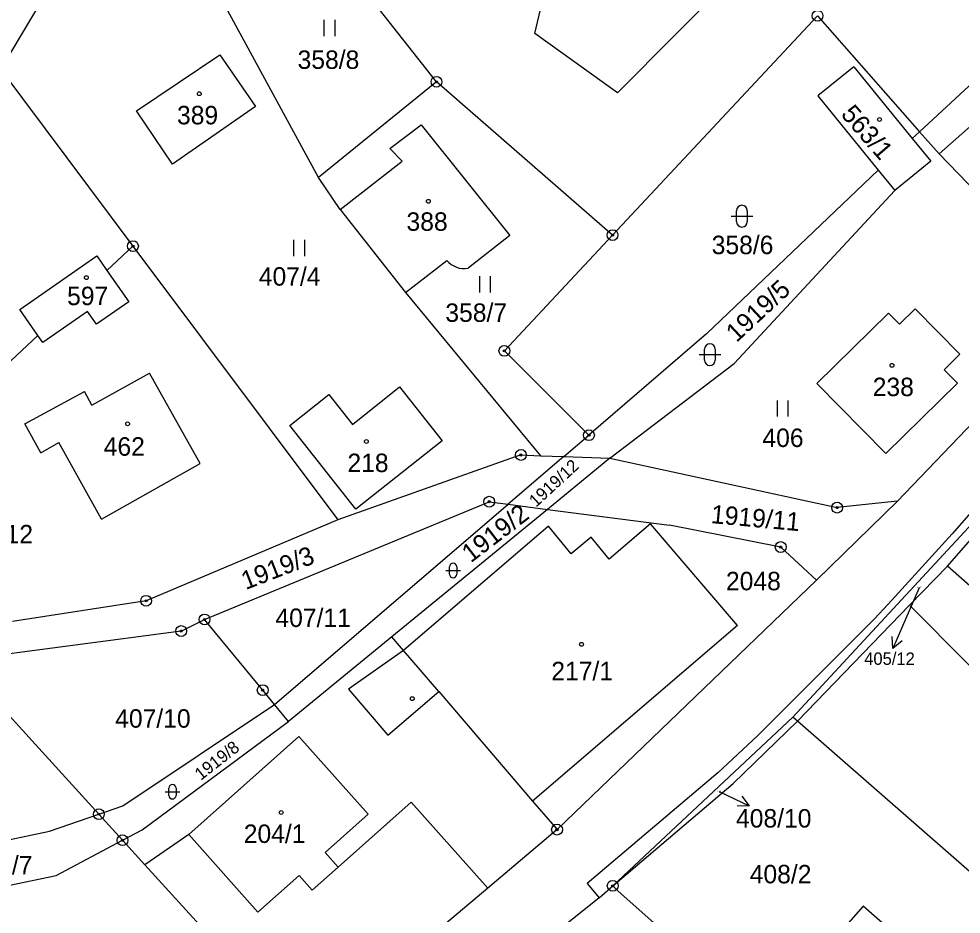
# Model space of a CAD drawing. Extents: x -445050 to -440454, y -1134563 to -1129741.
# Drawn here: x -442831.5 to -442744.7, y -1131095.9 to -1131013.5 of the extents above; entities that cross this region are included whole.
import ezdxf

# ---------------------------------------------------------------- set-up
doc = ezdxf.new("R2010")
doc.units = 0
for name, color, linetype in [('Vrstva 1', 7, 'Continuous'), ('Vrstva 16', 7, 'Continuous'), ('Vrstva 18', 7, 'Continuous'), ('Vrstva 19', 7, 'Continuous'), ('Vrstva 24', 7, 'Continuous'), ('Vrstva 25', 7, 'Continuous'), ('Vrstva 3', 7, 'Continuous'), ('Vrstva 37', 7, 'Continuous'), ('Vrstva 4', 7, 'Continuous'), ('Vrstva 6', 7, 'Continuous')]:
    doc.layers.add(name, color=color, linetype=linetype)

msp = doc.modelspace()

# ---------------------------------------------------------------- linework, layer by layer
at = {"layer": 'Vrstva 1'}
for points in [[(-442833.2, -1131018.12), (-442820.71, -1130997.18)], [(-442680.45, -1130998.49), (-442682.49, -1130998.44), (-442687.19, -1131000.32), (-442692.62, -1131004.7), (-442700.9, -1131011.92), (-442710.05, -1131020.8), (-442718.64, -1131029.65), (-442729.58, -1131042.35), (-442734.04, -1131047.81), (-442745.5, -1131060.91), (-442751.07, -1131067.01), (-442752.63, -1131068.7), (-442763.45, -1131079.5), (-442767.1, -1131082.91), (-442779.14, -1131093.12), (-442778.04, -1131094.43)], [(-442754.98, -1130998.74), (-442776.36, -1131020.27)], [(-442793.04, -1131019.25), (-442805.78, -1131003.06)], [(-442783.98, -1131014.8), (-442781.38, -1131003.85)], [(-442748.51, -1131023.86), (-442727.43, -1131004.32)], [(-442725.82, -1131007.43), (-442746.72, -1131025.9)], [(-442803.93, -1131028.07), (-442812.87, -1131011.62)], [(-442757.92, -1131013.17), (-442776.81, -1131033.38)], [(-442757.92, -1131013.17), (-442748.51, -1131023.86)], [(-442776.36, -1131020.27), (-442783.98, -1131014.8)], [(-442820.69, -1131021.93), (-442813, -1131016.75)], [(-442813, -1131016.75), (-442809.71, -1131021.54)], [(-442754.57, -1131017.86), (-442757.88, -1131020.55)], [(-442754.57, -1131017.86), (-442749.18, -1131024.48)], [(-442833.2, -1131018.12), (-442821.02, -1131034.39)], [(-442793.04, -1131019.25), (-442803.93, -1131028.07)], [(-442776.81, -1131033.38), (-442793.04, -1131019.25)], [(-442757.88, -1131020.55), (-442752.34, -1131027.38)], [(-442817.37, -1131026.85), (-442820.69, -1131021.93)], [(-442809.71, -1131021.54), (-442817.37, -1131026.85)], [(-442797.33, -1131025.41), (-442794.44, -1131023.2)], [(-442794.44, -1131023.2), (-442786.28, -1131033.41)], [(-442749.18, -1131024.48), (-442748.51, -1131023.86)], [(-442748.51, -1131023.86), (-442746.72, -1131025.9)], [(-442749.18, -1131024.48), (-442747.48, -1131026.57)], [(-442796.19, -1131026.56), (-442797.33, -1131025.41)], [(-442801.91, -1131031.02), (-442796.19, -1131026.56)], [(-442747.48, -1131026.57), (-442750.8, -1131029.27)], [(-442746.72, -1131025.9), (-442741.4, -1131031.39)], [(-442752.34, -1131027.38), (-442768.15, -1131042.47)], [(-442752.34, -1131027.38), (-442750.8, -1131029.27)], [(-442801.91, -1131031.02), (-442803.93, -1131028.07)], [(-442765.6, -1131045.19), (-442750.8, -1131029.27)], [(-442801.91, -1131031.02), (-442795.89, -1131038.66)], [(-442786.28, -1131033.41), (-442790.12, -1131036.43)], [(-442776.81, -1131033.38), (-442786.78, -1131044.04)], [(-442823.41, -1131036.63), (-442821.02, -1131034.39)], [(-442821.02, -1131034.39), (-442802.14, -1131059.61)], [(-442829.79, -1131042.61), (-442831.45, -1131040.22), (-442824.34, -1131035.29), (-442823.41, -1131036.63)], [(-442795.89, -1131038.66), (-442792.09, -1131035.7)], [(-442823.41, -1131036.63), (-442821.41, -1131039.52)], [(-442795.89, -1131038.66), (-442783.46, -1131053.7)], [(-442821.41, -1131039.52), (-442824.38, -1131041.57), (-442825.2, -1131040.4), (-442829.33, -1131043.26), (-442829.79, -1131042.61)], [(-442751.37, -1131040.56), (-442757.97, -1131047.05)], [(-442750.36, -1131041.58), (-442751.37, -1131040.56)], [(-442748.92, -1131040.16), (-442750.36, -1131041.58)], [(-442744.79, -1131044.36), (-442748.92, -1131040.16)], [(-442750.55, -1131057.88), (-442734.37, -1131040.99)], [(-442845.58, -1131057.41), (-442829.79, -1131042.61)], [(-442768.15, -1131042.47), (-442778.99, -1131051.81)], [(-442786.78, -1131044.04), (-442778.99, -1131051.81)], [(-442746.24, -1131045.78), (-442744.79, -1131044.36)], [(-442777.06, -1131053.94), (-442765.6, -1131045.19)], [(-442745.02, -1131047.02), (-442746.24, -1131045.78)], [(-442824.8, -1131049.04), (-442819.5, -1131046.1)], [(-442814.83, -1131054.43), (-442819.5, -1131046.1)], [(-442800.79, -1131050.81), (-442796.45, -1131047.37)], [(-442796.45, -1131047.37), (-442792.52, -1131052.34)], [(-442751.62, -1131053.5), (-442757.97, -1131047.05)], [(-442745.02, -1131047.02), (-442751.62, -1131053.5)], [(-442830.97, -1131050.75), (-442825.49, -1131047.77)], [(-442824.8, -1131049.04), (-442825.49, -1131047.77)], [(-442806.55, -1131050.91), (-442802.96, -1131048.07)], [(-442802.96, -1131048.07), (-442800.79, -1131050.81)], [(-442829.51, -1131053.45), (-442830.97, -1131050.75)], [(-442800.46, -1131058.62), (-442806.55, -1131050.91)], [(-442781.3, -1131053.78), (-442778.99, -1131051.81)], [(-442735.52, -1131051.16), (-442760.18, -1131077.8)], [(-442745.94, -1131063.87), (-442735.13, -1131051.5)], [(-442829.51, -1131053.45), (-442827.84, -1131052.49)], [(-442823.93, -1131059.54), (-442827.84, -1131052.49)], [(-442792.52, -1131052.34), (-442800.46, -1131058.62)], [(-442823.93, -1131059.54), (-442814.83, -1131054.43)], [(-442785.26, -1131053.63), (-442802.14, -1131059.61)], [(-442785.26, -1131053.63), (-442783.46, -1131053.7)], [(-442783.46, -1131053.7), (-442781.3, -1131053.78)], [(-442781.3, -1131053.78), (-442777.06, -1131053.94)], [(-442777.06, -1131053.94), (-442756.11, -1131058.48)], [(-442814.42, -1131068.79), (-442788.18, -1131057.94)], [(-442788.18, -1131057.94), (-442786.42, -1131058.17)], [(-442758.02, -1131065.18), (-442750.55, -1131057.88)], [(-442750.55, -1131057.88), (-442756.11, -1131058.48)], [(-442807.97, -1131076.63), (-442786.42, -1131058.17)], [(-442782.82, -1131058.65), (-442797.15, -1131070.38)], [(-442786.42, -1131058.17), (-442782.82, -1131058.65)], [(-442782.82, -1131058.65), (-442771.56, -1131060.1)], [(-442802.14, -1131059.61), (-442819.8, -1131067.07)], [(-442782.71, -1131060.19), (-442796.07, -1131071.64)], [(-442780.62, -1131062.73), (-442782.71, -1131060.19)], [(-442773.3, -1131059.99), (-442777.12, -1131063.22)], [(-442765.29, -1131069.34), (-442773.3, -1131059.99)], [(-442761.31, -1131062.12), (-442771.56, -1131060.1)], [(-442778.78, -1131061.22), (-442780.62, -1131062.73)], [(-442777.12, -1131063.22), (-442778.78, -1131061.22)], [(-442758.02, -1131065.18), (-442761.31, -1131062.12)], [(-442749.43, -1131067.48), (-442745.94, -1131063.87)], [(-442736.36, -1131072.33), (-442745.94, -1131063.87)], [(-442758.02, -1131065.18), (-442781.93, -1131088.15)], [(-442819.8, -1131067.07), (-442832.12, -1131068.99)], [(-442759.77, -1131078.16), (-442749.43, -1131067.48)], [(-442738.59, -1131078.37), (-442749.43, -1131067.48)], [(-442816.57, -1131069.86), (-442814.42, -1131068.79)], [(-442809.06, -1131075.3), (-442814.42, -1131068.79)], [(-442816.57, -1131069.86), (-442837.06, -1131072.58)], [(-442765.29, -1131069.34), (-442784.18, -1131085.52)], [(-442797.15, -1131070.38), (-442806.69, -1131078.18)], [(-442796.07, -1131071.64), (-442797.15, -1131070.38)], [(-442792.82, -1131075.43), (-442796.07, -1131071.64)], [(-442837.06, -1131072.58), (-442824.16, -1131086.73)], [(-442807.97, -1131076.63), (-442809.06, -1131075.3)], [(-442792.82, -1131075.43), (-442784.18, -1131085.52)], [(-442821.95, -1131085.97), (-442807.97, -1131076.63)], [(-442806.69, -1131078.18), (-442807.97, -1131076.63)], [(-442776.8, -1131093.33), (-442760.18, -1131077.8)], [(-442759.77, -1131078.16), (-442760.18, -1131077.8)], [(-442820.18, -1131088.17), (-442806.69, -1131078.18)], [(-442776.8, -1131093.33), (-442765.69, -1131083.9), (-442759.77, -1131078.16)], [(-442727.34, -1131106.47), (-442759.77, -1131078.16)], [(-442802.1, -1131091.6), (-442795.37, -1131085.62)], [(-442788.32, -1131093.55), (-442795.37, -1131085.62)], [(-442784.18, -1131085.52), (-442781.93, -1131088.15)], [(-442824.16, -1131086.73), (-442821.95, -1131085.97)], [(-442828.71, -1131088.3), (-442824.16, -1131086.73)], [(-442824.16, -1131086.73), (-442821.98, -1131089.13)], [(-442855.31, -1131093.9), (-442828.71, -1131088.3)], [(-442821.98, -1131089.13), (-442820.18, -1131088.17)], [(-442781.93, -1131088.15), (-442788.32, -1131093.55)], [(-442828.09, -1131092.38), (-442821.98, -1131089.13)], [(-442821.98, -1131089.13), (-442819.91, -1131091.39)], [(-442815.88, -1131088.6), (-442819.91, -1131091.39)], [(-442815.88, -1131088.6), (-442809.5, -1131095.77)], [(-442819.91, -1131091.39), (-442805.07, -1131107.68)], [(-442804.49, -1131093.73), (-442802.1, -1131091.6)], [(-442833.28, -1131093.46), (-442828.09, -1131092.38)], [(-442809.5, -1131095.77), (-442805.69, -1131092.39)], [(-442805.69, -1131092.39), (-442804.49, -1131093.73)], [(-442788.32, -1131093.55), (-442805.07, -1131107.68)], [(-442778.04, -1131094.43), (-442776.8, -1131093.33)], [(-442776.8, -1131093.33), (-442776.33, -1131093.78)], [(-442776.33, -1131093.78), (-442756.1, -1131111.75)], [(-442778.04, -1131094.43), (-442801.17, -1131112.96)], [(-442753.7, -1131095.21), (-442761.69, -1131104.28)], [(-442748.14, -1131100.09), (-442753.7, -1131095.21)]]:
    msp.add_lwpolyline(points, dxfattribs=at)
msp.add_arc((-442790.476, -1131034.368), 2.093, 219.5379, 279.79688, dxfattribs=at)
at = {"layer": 'Vrstva 16'}
for p, q in [((-442749.78, -1131068.71), (-442750.97, -1131071.464)), ((-442766.93, -1131084.68), (-442764.212, -1131085.95))]:
    msp.add_line(p, q, dxfattribs=at)
for points in [[(-442748.55, -1131065.87), (-442749.78, -1131068.71)], [(-442750.114, -1131070.744), (-442750.97, -1131071.464), (-442751.032, -1131070.348)], [(-442766.98, -1131084.66), (-442766.93, -1131084.68)], [(-442764.906, -1131085.074), (-442764.212, -1131085.95), (-442765.33, -1131085.98)]]:
    msp.add_lwpolyline(points, dxfattribs=at)
at = {"layer": 'Vrstva 24'}
for centre, radius in [((-442757.92, -1131013.17), 0.5), ((-442793.04, -1131019.25), 0.5), ((-442793.04, -1131019.25), 0.1), ((-442776.81, -1131033.38), 0.5), ((-442776.81, -1131033.38), 0.1), ((-442821.02, -1131034.39), 0.5), ((-442821.02, -1131034.39), 0.1), ((-442786.78, -1131044.04), 0.5), ((-442786.78, -1131044.04), 0.1), ((-442778.99, -1131051.81), 0.5), ((-442778.99, -1131051.81), 0.1), ((-442785.26, -1131053.63), 0.5), ((-442785.26, -1131053.63), 0.1), ((-442788.18, -1131057.94), 0.5), ((-442788.18, -1131057.94), 0.1), ((-442756.11, -1131058.48), 0.5), ((-442756.11, -1131058.48), 0.1), ((-442761.31, -1131062.12), 0.5), ((-442761.31, -1131062.12), 0.1), ((-442819.8, -1131067.07), 0.5), ((-442819.8, -1131067.07), 0.1), ((-442814.42, -1131068.79), 0.5), ((-442814.42, -1131068.79), 0.1), ((-442816.57, -1131069.86), 0.5), ((-442816.57, -1131069.86), 0.1), ((-442809.06, -1131075.3), 0.5), ((-442809.06, -1131075.3), 0.1), ((-442824.16, -1131086.73), 0.5), ((-442824.16, -1131086.73), 0.1), ((-442781.93, -1131088.15), 0.5), ((-442781.93, -1131088.15), 0.1), ((-442821.98, -1131089.13), 0.5), ((-442821.98, -1131089.13), 0.1), ((-442776.8, -1131093.33), 0.5), ((-442776.8, -1131093.33), 0.1)]:
    msp.add_circle(centre, radius, dxfattribs=at)
at = {"layer": 'Vrstva 25'}
for p, q in [((-442803.38, -1131015.05), (-442803.38, -1131013.55)), ((-442802.38, -1131015.05), (-442802.38, -1131013.55)), ((-442765.89, -1131031.63), (-442763.89, -1131031.63)), ((-442765.39, -1131032.13), (-442765.39, -1131031.13)), ((-442764.39, -1131031.13), (-442764.39, -1131032.13)), ((-442806.19, -1131035.32), (-442806.19, -1131033.82)), ((-442805.19, -1131035.32), (-442805.19, -1131033.82)), ((-442789.05, -1131038.66), (-442789.05, -1131037.16)), ((-442788.05, -1131038.66), (-442788.05, -1131037.16)), ((-442768.34, -1131044.89), (-442768.34, -1131043.89)), ((-442767.34, -1131043.89), (-442767.34, -1131044.89)), ((-442768.84, -1131044.39), (-442766.84, -1131044.39)), ((-442761.62, -1131050.1), (-442761.62, -1131048.6)), ((-442760.62, -1131050.1), (-442760.62, -1131048.6)), ((-442791.845, -1131064.615), (-442791.845, -1131063.945)), ((-442791.175, -1131063.945), (-442791.175, -1131064.615)), ((-442792.18, -1131064.28), (-442790.84, -1131064.28)), ((-442818.05, -1131084.66), (-442816.71, -1131084.66)), ((-442817.715, -1131084.995), (-442817.715, -1131084.325)), ((-442817.045, -1131084.325), (-442817.045, -1131084.995))]:
    msp.add_line(p, q, dxfattribs=at)
for centre in [(-442814.9, -1131020.35), (-442752.21, -1131022.72), (-442793.79, -1131030.26), (-442825.31, -1131037.29), (-442751.06, -1131045.38), (-442821.51, -1131050.76), (-442799.5, -1131052.39), (-442779.67, -1131071.08), (-442795.27, -1131076.08), (-442807.36, -1131086.57)]:
    msp.add_circle(centre, 0.175, dxfattribs=at)
for centre, radius, start, end in [((-442764.89, -1131031.13), 0.5, 0, 180), ((-442764.89, -1131032.13), 0.5, 180, 0), ((-442767.84, -1131043.89), 0.5, 0, 180), ((-442767.84, -1131044.89), 0.5, 180, 0), ((-442791.51, -1131063.945), 0.335, 0, 180), ((-442791.51, -1131064.615), 0.335, 180, 0), ((-442817.38, -1131084.325), 0.335, 0, 180), ((-442817.38, -1131084.995), 0.335, 180, 0)]:
    msp.add_arc(centre, radius, start, end, dxfattribs=at)
at = {"layer": 'Vrstva 3'}
for points in [[(-442820.69, -1131021.93), (-442813, -1131016.75)], [(-442813, -1131016.75), (-442809.71, -1131021.54)], [(-442754.57, -1131017.86), (-442757.88, -1131020.55)], [(-442754.57, -1131017.86), (-442749.18, -1131024.48)], [(-442757.88, -1131020.55), (-442752.34, -1131027.38)], [(-442817.37, -1131026.85), (-442820.69, -1131021.93)], [(-442809.71, -1131021.54), (-442817.37, -1131026.85)], [(-442797.33, -1131025.41), (-442794.44, -1131023.2)], [(-442794.44, -1131023.2), (-442786.28, -1131033.41)], [(-442749.18, -1131024.48), (-442747.48, -1131026.57)], [(-442796.19, -1131026.56), (-442797.33, -1131025.41)], [(-442801.91, -1131031.02), (-442796.19, -1131026.56)], [(-442747.48, -1131026.57), (-442750.8, -1131029.27)], [(-442752.34, -1131027.38), (-442750.8, -1131029.27)], [(-442801.91, -1131031.02), (-442795.89, -1131038.66)], [(-442786.28, -1131033.41), (-442790.12, -1131036.43)], [(-442829.79, -1131042.61), (-442831.45, -1131040.22), (-442824.34, -1131035.29), (-442823.41, -1131036.63)], [(-442795.89, -1131038.66), (-442792.09, -1131035.7)], [(-442823.41, -1131036.63), (-442821.41, -1131039.52)], [(-442821.41, -1131039.52), (-442824.38, -1131041.57), (-442825.2, -1131040.4), (-442829.33, -1131043.26), (-442829.79, -1131042.61)], [(-442751.37, -1131040.56), (-442757.97, -1131047.05)], [(-442750.36, -1131041.58), (-442751.37, -1131040.56)], [(-442748.92, -1131040.16), (-442750.36, -1131041.58)], [(-442744.79, -1131044.36), (-442748.92, -1131040.16)], [(-442746.24, -1131045.78), (-442744.79, -1131044.36)], [(-442745.02, -1131047.02), (-442746.24, -1131045.78)], [(-442824.8, -1131049.04), (-442819.5, -1131046.1)], [(-442814.83, -1131054.43), (-442819.5, -1131046.1)], [(-442800.79, -1131050.81), (-442796.45, -1131047.37)], [(-442796.45, -1131047.37), (-442792.52, -1131052.34)], [(-442751.62, -1131053.5), (-442757.97, -1131047.05)], [(-442745.02, -1131047.02), (-442751.62, -1131053.5)], [(-442830.97, -1131050.75), (-442825.49, -1131047.77)], [(-442824.8, -1131049.04), (-442825.49, -1131047.77)], [(-442806.55, -1131050.91), (-442802.96, -1131048.07)], [(-442802.96, -1131048.07), (-442800.79, -1131050.81)], [(-442829.51, -1131053.45), (-442830.97, -1131050.75)], [(-442800.46, -1131058.62), (-442806.55, -1131050.91)], [(-442829.51, -1131053.45), (-442827.84, -1131052.49)], [(-442823.93, -1131059.54), (-442827.84, -1131052.49)], [(-442792.52, -1131052.34), (-442800.46, -1131058.62)], [(-442823.93, -1131059.54), (-442814.83, -1131054.43)], [(-442782.71, -1131060.19), (-442796.07, -1131071.64)], [(-442780.62, -1131062.73), (-442782.71, -1131060.19)], [(-442773.3, -1131059.99), (-442777.12, -1131063.22)], [(-442765.29, -1131069.34), (-442773.3, -1131059.99)], [(-442778.78, -1131061.22), (-442780.62, -1131062.73)], [(-442777.12, -1131063.22), (-442778.78, -1131061.22)], [(-442765.29, -1131069.34), (-442784.18, -1131085.52)], [(-442792.82, -1131075.43), (-442796.07, -1131071.64)], [(-442792.82, -1131075.43), (-442784.18, -1131085.52)], [(-442805.72, -1131079.56), (-442815.88, -1131088.6)], [(-442799.33, -1131086.73), (-442805.72, -1131079.56)], [(-442803.29, -1131090.25), (-442799.33, -1131086.73)], [(-442815.88, -1131088.6), (-442809.5, -1131095.77)], [(-442802.1, -1131091.6), (-442803.29, -1131090.25)], [(-442804.49, -1131093.73), (-442802.1, -1131091.6)], [(-442809.5, -1131095.77), (-442805.69, -1131092.39)], [(-442805.69, -1131092.39), (-442804.49, -1131093.73)], [(-442753.7, -1131095.21), (-442761.69, -1131104.28)], [(-442748.14, -1131100.09), (-442753.7, -1131095.21)]]:
    msp.add_lwpolyline(points, dxfattribs=at)
msp.add_arc((-442790.476, -1131034.368), 2.093, 219.5379, 279.79688, dxfattribs=at)
at = {"layer": 'Vrstva 37'}
for centre in [(-442814.9, -1131020.35), (-442752.21, -1131022.72), (-442793.79, -1131030.26), (-442825.31, -1131037.29), (-442751.06, -1131045.38), (-442821.51, -1131050.76), (-442799.5, -1131052.39), (-442779.67, -1131071.08), (-442807.36, -1131086.57)]:
    msp.add_circle(centre, 0.175, dxfattribs=at)
at = {"layer": 'Vrstva 4'}
for points in [[(-442796.07, -1131071.64), (-442801.14, -1131075.2)], [(-442801.14, -1131075.2), (-442797.52, -1131079.46)], [(-442797.52, -1131079.46), (-442792.82, -1131075.43)], [(-442805.72, -1131079.56), (-442815.88, -1131088.6)], [(-442799.33, -1131086.73), (-442805.72, -1131079.56)], [(-442803.29, -1131090.25), (-442799.33, -1131086.73)], [(-442802.1, -1131091.6), (-442803.29, -1131090.25)]]:
    msp.add_lwpolyline(points, dxfattribs=at)
at = {"layer": 'Vrstva 6'}
for points in [[(-442781.3, -1131053.78), (-442786.42, -1131058.17)], [(-442777.06, -1131053.94), (-442782.82, -1131058.65)]]:
    msp.add_lwpolyline(points, dxfattribs=at)

# ---------------------------------------------------------------- texts
at = {"layer": 'Vrstva 16'}
for s, height, p in [('405/12', 1.14, (-442753.616, -1131072.97)), ('408/10', 1.7, (-442765.433, -1131087.96))]:
    msp.add_text(s, height=height, dxfattribs=at).set_placement(p)
at = {"layer": 'Vrstva 18'}
for s, height, p in [('358/8', 1.7, (-442805.843, -1131018.06)), ('358/6', 1.7, (-442767.674, -1131035.13)), ('407/4', 1.7, (-442809.418, -1131038.03)), ('358/7', 1.7, (-442792.223, -1131041.37)), ('406', 1.7, (-442762.998, -1131052.9)), ('407/12', 1.7, (-442837.178, -1131061.78)), ('2048', 1.7, (-442766.36, -1131066.1)), ('405/12', 0.1, (-442748.765, -1131065.87)), ('407/11', 1.7, (-442807.885, -1131069.48)), ('407/10', 1.7, (-442822.653, -1131078.76)), ('408/10', 0.1, (-442767.198, -1131084.66)), ('1919/7', 1.7, (-442837.232, -1131092.27)), ('408/2', 1.7, (-442764.168, -1131093.1))]:
    msp.add_text(s, height=height, dxfattribs=at).set_placement(p)
for s, height, rotation, p in [('1919/5', 1.7, 42.9174, (-442765.383, -1131043.322)), ('1919/12', 1.14, 42.58053, (-442783.868, -1131058.499)), ('1919/2', 1.7, 37.4868, (-442789.876, -1131063.622)), ('1919/11', 1.7, 354.7746, (-442767.796, -1131059.906)), ('1919/3', 1.7, 21.2247, (-442810.627, -1131066.083)), ('1919/8', 1.14, 38.08161, (-442814.764, -1131083.664))]:
    msp.add_text(s, height=height, rotation=rotation, dxfattribs=at).set_placement(p)
at = {"layer": 'Vrstva 19'}
for s, p in [('389', (-442816.957, -1131023.17)), ('388', (-442795.802, -1131032.98)), ('597', (-442827.087, -1131039.83)), ('238', (-442752.832, -1131048.21)), ('462', (-442823.713, -1131053.7)), ('218', (-442801.249, -1131055.21)), ('217/1', (-442782.457, -1131074.39)), ('204/1', (-442810.805, -1131089.38))]:
    msp.add_text(s, height=1.7, dxfattribs=at).set_placement(p)
msp.add_text('563/1', height=1.7, rotation=310.8969, dxfattribs=at).set_placement((-442755.842, -1131022.289))

doc.saveas('drawing.dxf')
